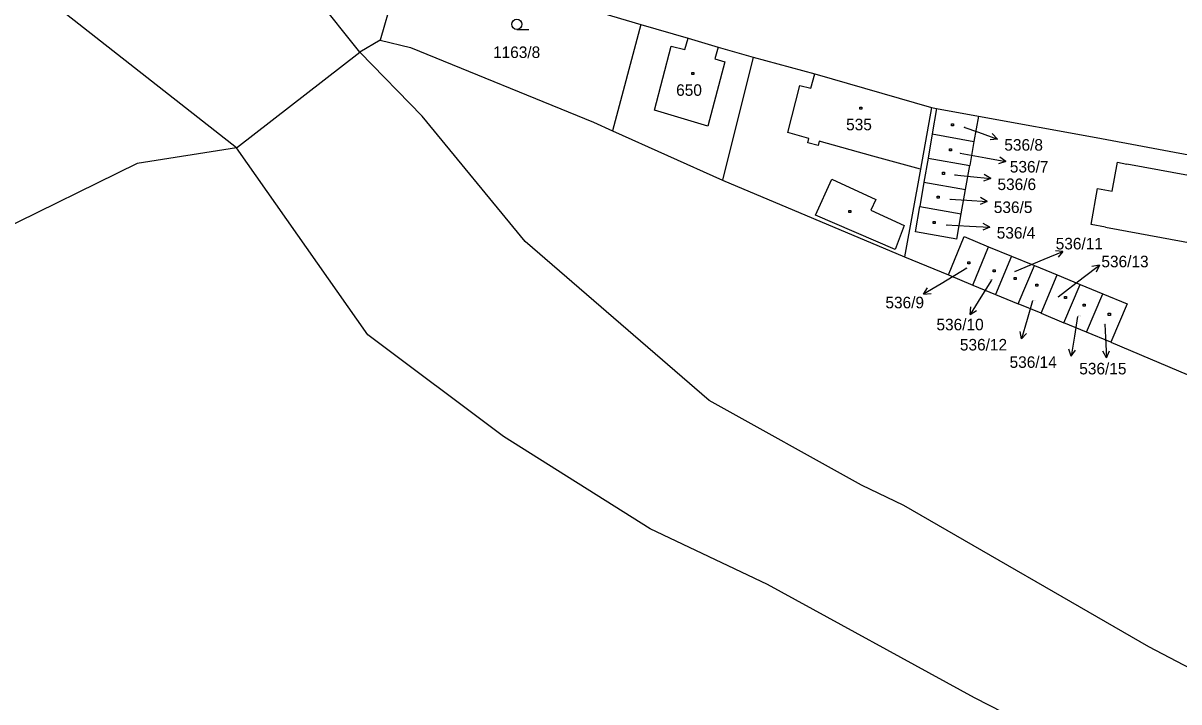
# Model space of a CAD drawing. Extents: x -795483 to -789093, y -1112258 to -1108741.
# Drawn here: x -792326 to -792155.7, y -1110149.8 to -1110049.9 of the extents above; entities that cross this region are included whole.
import ezdxf

# ---------------------------------------------------------------- set-up
doc = ezdxf.new("R2010")
doc.units = 0
for name, color, linetype in [('Komunikace', 7, 'Continuous'), ('Vrstva 1', 7, 'Continuous'), ('Vrstva 14', 7, 'Continuous'), ('Vrstva 15', 7, 'Continuous'), ('Vrstva 16', 7, 'Continuous'), ('Vrstva 2', 7, 'Continuous'), ('Vrstva 23', 7, 'Continuous'), ('Vrstva 25', 7, 'Continuous')]:
    doc.layers.add(name, color=color, linetype=linetype)

msp = doc.modelspace()

# ---------------------------------------------------------------- linework, layer by layer
at = {"layer": 'Komunikace'}
for p, q in [((-792187.44, -1110065.17), (-792185.28, -1110065.94)), ((-792187.97, -1110069.04), (-792184.17, -1110069.73)), ((-792188.78, -1110072.22), (-792186.45, -1110072.45)), ((-792189.49, -1110075.77), (-792186.99, -1110075.93)), ((-792190.04, -1110079.59), (-792186.57, -1110079.76)), ((-792179.91, -1110086.43), (-792175.58, -1110084.63)), ((-792186.99, -1110085.96), (-792190.78, -1110088.24)), ((-792173.51, -1110090.19), (-792169.83, -1110087.35)), ((-792183.36, -1110087.71), (-792184.9, -1110090.21)), ((-792177.3, -1110090.77), (-792178.09, -1110093.49)), ((-792170.66, -1110093.05), (-792171.13, -1110095.97)), ((-792166.66, -1110094.22), (-792166.56, -1110096.14))]:
    msp.add_line(p, q, dxfattribs=at)
at = {"layer": 'Vrstva 1'}
for p, q in [((-792294.56, -1110068.22), (-792338.95, -1110033.41)), ((-792276.39, -1110054.16), (-792289.1, -1110038.19)), ((-792269.72, -1110039.81), (-792273.43, -1110052.38)), ((-792269.72, -1110039.81), (-792234.98, -1110050.06)), ((-792234.98, -1110050.06), (-792239.19, -1110065.72)), ((-792234.98, -1110050.06), (-792228.04, -1110052.11)), ((-792273.43, -1110052.38), (-792276.39, -1110054.16)), ((-792273.43, -1110052.38), (-792268.94, -1110053.48)), ((-792228.04, -1110052.11), (-792223.61, -1110053.42)), ((-792294.56, -1110068.22), (-792276.39, -1110054.16)), ((-792267.24, -1110063.58), (-792276.39, -1110054.16)), ((-792268.94, -1110053.48), (-792241.96, -1110064.47)), ((-792223.61, -1110053.42), (-792218.43, -1110054.87)), ((-792218.43, -1110054.87), (-792222.98, -1110073.01)), ((-792218.43, -1110054.87), (-792209.35, -1110057.34)), ((-792209.35, -1110057.34), (-792192.18, -1110062.31)), ((-792252.06, -1110082.02), (-792267.24, -1110063.58)), ((-792192.18, -1110062.31), (-792193.82, -1110071.4)), ((-792192.18, -1110062.31), (-792191.44, -1110062.44)), ((-792191.44, -1110062.44), (-792192.08, -1110066.18)), ((-792191.44, -1110062.44), (-792185.28, -1110063.55)), ((-792185.28, -1110063.55), (-792185.93, -1110067.28)), ((-792185.28, -1110063.55), (-792167.93, -1110066.73)), ((-792241.96, -1110064.47), (-792239.19, -1110065.72)), ((-792239.19, -1110065.72), (-792222.98, -1110073.01)), ((-792192.08, -1110066.18), (-792192.69, -1110069.75)), ((-792192.08, -1110066.18), (-792185.93, -1110067.28)), ((-792167.93, -1110066.73), (-792119.01, -1110075.8)), ((-792294.56, -1110068.22), (-792309.21, -1110070.53)), ((-792275.24, -1110095.78), (-792294.56, -1110068.22)), ((-792185.93, -1110067.28), (-792186.55, -1110070.83)), ((-792192.69, -1110069.75), (-792193.3, -1110073.31)), ((-792192.69, -1110069.75), (-792186.55, -1110070.83)), ((-792165.57, -1110074.61), (-792164.79, -1110070.36)), ((-792164.79, -1110070.36), (-792163.39, -1110070.62)), ((-792309.21, -1110070.53), (-792356.78, -1110093.85)), ((-792193.82, -1110071.4), (-792196.16, -1110084.26)), ((-792187.17, -1110074.38), (-792186.55, -1110070.83)), ((-792145.08, -1110074), (-792163.39, -1110070.62)), ((-792222.98, -1110073.01), (-792196.16, -1110084.26)), ((-792193.3, -1110073.31), (-792193.91, -1110076.88)), ((-792193.3, -1110073.31), (-792187.17, -1110074.38)), ((-792187.79, -1110077.93), (-792187.17, -1110074.38)), ((-792168.64, -1110079.53), (-792167.73, -1110074.21)), ((-792167.73, -1110074.21), (-792165.57, -1110074.61)), ((-792194.55, -1110080.62), (-792193.91, -1110076.88)), ((-792193.91, -1110076.88), (-792187.79, -1110077.93)), ((-792188.44, -1110081.66), (-792187.79, -1110077.93)), ((-792166.54, -1110079.92), (-792168.64, -1110079.53)), ((-792166.54, -1110079.92), (-792146.82, -1110083.56)), ((-792224.96, -1110105.43), (-792252.06, -1110082.02)), ((-792188.44, -1110081.66), (-792194.55, -1110080.62)), ((-792186.09, -1110088.43), (-792183.76, -1110082.79)), ((-792183.76, -1110082.79), (-792180.39, -1110084.18)), ((-792196.16, -1110084.26), (-792189.7, -1110086.94)), ((-792180.39, -1110084.18), (-792182.74, -1110089.82)), ((-792180.39, -1110084.18), (-792177.03, -1110085.56)), ((-792179.39, -1110091.21), (-792177.03, -1110085.56)), ((-792177.03, -1110085.56), (-792173.66, -1110086.95)), ((-792189.7, -1110086.94), (-792186.09, -1110088.43)), ((-792176.04, -1110092.59), (-792173.66, -1110086.95)), ((-792173.66, -1110086.95), (-792170.29, -1110088.34)), ((-792186.09, -1110088.43), (-792182.74, -1110089.82)), ((-792172.69, -1110093.98), (-792170.29, -1110088.34)), ((-792170.29, -1110088.34), (-792166.92, -1110089.72)), ((-792182.74, -1110089.82), (-792179.39, -1110091.21)), ((-792169.33, -1110095.37), (-792166.92, -1110089.72)), ((-792166.92, -1110089.72), (-792163.33, -1110091.2)), ((-792176.04, -1110092.59), (-792179.39, -1110091.21)), ((-792163.33, -1110091.2), (-792165.77, -1110096.84)), ((-792176.04, -1110092.59), (-792172.69, -1110093.98)), ((-792169.33, -1110095.37), (-792172.69, -1110093.98)), ((-792255.24, -1110110.74), (-792275.24, -1110095.78)), ((-792165.77, -1110096.84), (-792169.33, -1110095.37)), ((-792165.77, -1110096.84), (-792152.88, -1110102.28)), ((-792202.48, -1110117.91), (-792224.96, -1110105.43)), ((-792233.64, -1110124.34), (-792255.24, -1110110.74)), ((-792196.27, -1110120.89), (-792202.48, -1110117.91)), ((-792160.15, -1110141.69), (-792196.27, -1110120.89)), ((-792216.32, -1110132.52), (-792233.64, -1110124.34)), ((-792185.85, -1110149.21), (-792216.32, -1110132.52)), ((-792117.26, -1110164.25), (-792160.15, -1110141.69)), ((-792168.85, -1110157.86), (-792185.85, -1110149.21))]:
    msp.add_line(p, q, dxfattribs=at)
msp.add_lwpolyline([(-792189.7, -1110086.94), (-792187.39, -1110081.3), (-792183.76, -1110082.79)], dxfattribs=at)
at = {"layer": 'Vrstva 16'}
for p, q in [((-792185.28, -1110065.94), (-792182.45, -1110066.95)), ((-792182.45, -1110066.95), (-792183.56, -1110067.08)), ((-792182.45, -1110066.95), (-792183.23, -1110066.14)), ((-792184.17, -1110069.73), (-792181.22, -1110070.27)), ((-792181.22, -1110070.27), (-792182.29, -1110070.58)), ((-792181.22, -1110070.27), (-792182.11, -1110069.6)), ((-792186.45, -1110072.45), (-792183.46, -1110072.75)), ((-792183.46, -1110072.75), (-792184.51, -1110073.15)), ((-792183.46, -1110072.75), (-792184.41, -1110072.15)), ((-792186.99, -1110075.93), (-792184, -1110076.13)), ((-792184, -1110076.13), (-792185.03, -1110076.56)), ((-792184, -1110076.13), (-792184.96, -1110075.56)), ((-792186.57, -1110079.76), (-792183.57, -1110079.9)), ((-792183.57, -1110079.9), (-792184.6, -1110080.35)), ((-792183.57, -1110079.9), (-792184.55, -1110079.36)), ((-792175.58, -1110084.63), (-792172.81, -1110083.48)), ((-792172.81, -1110083.48), (-792173.92, -1110083.4)), ((-792172.81, -1110083.48), (-792173.54, -1110084.32)), ((-792169.83, -1110087.35), (-792167.45, -1110085.52)), ((-792167.45, -1110085.52), (-792168.55, -1110085.73)), ((-792167.45, -1110085.52), (-792167.94, -1110086.52)), ((-792190.78, -1110088.24), (-792193.35, -1110089.78)), ((-792193.35, -1110089.78), (-792192.75, -1110088.84)), ((-792193.35, -1110089.78), (-792192.24, -1110089.7)), ((-792184.9, -1110090.21), (-792186.48, -1110092.76)), ((-792186.48, -1110092.76), (-792186.38, -1110091.65)), ((-792186.48, -1110092.76), (-792185.53, -1110092.17)), ((-792178.09, -1110093.49), (-792178.92, -1110096.37)), ((-792178.92, -1110096.37), (-792179.13, -1110095.27)), ((-792178.92, -1110096.37), (-792178.17, -1110095.55)), ((-792171.13, -1110095.97), (-792171.61, -1110098.93)), ((-792166.56, -1110096.14), (-792166.41, -1110099.14)), ((-792171.61, -1110098.93), (-792171.94, -1110097.86)), ((-792171.61, -1110098.93), (-792170.96, -1110098.02)), ((-792166.41, -1110099.14), (-792166.96, -1110098.16)), ((-792166.41, -1110099.14), (-792165.96, -1110098.11))]:
    msp.add_line(p, q, dxfattribs=at)
at = {"layer": 'Vrstva 2'}
for p, q in [((-792233.01, -1110062.7), (-792230.52, -1110053.26)), ((-792230.52, -1110053.26), (-792228.52, -1110053.78)), ((-792228.52, -1110053.78), (-792228.04, -1110052.11)), ((-792223.61, -1110053.42), (-792224.11, -1110055.15)), ((-792222.61, -1110055.55), (-792225.15, -1110065.04)), ((-792224.11, -1110055.15), (-792222.61, -1110055.55)), ((-792209.96, -1110059.45), (-792209.35, -1110057.34)), ((-792213.34, -1110065.99), (-792211.58, -1110059.04)), ((-792211.58, -1110059.04), (-792209.96, -1110059.45)), ((-792225.15, -1110065.04), (-792233.01, -1110062.7)), ((-792210.26, -1110066.84), (-792213.34, -1110065.99)), ((-792210.4, -1110067.48), (-792210.26, -1110066.84)), ((-792208.89, -1110067.91), (-792210.4, -1110067.48)), ((-792208.71, -1110067.27), (-792208.89, -1110067.91)), ((-792200.8, -1110069.46), (-792208.71, -1110067.27)), ((-792193.82, -1110071.4), (-792200.8, -1110069.46)), ((-792209.26, -1110078.14), (-792206.88, -1110072.87)), ((-792206.88, -1110072.87), (-792200.38, -1110075.85)), ((-792200.38, -1110075.85), (-792201.1, -1110077.42)), ((-792197.52, -1110083.2), (-792209.26, -1110078.14)), ((-792201.1, -1110077.42), (-792196.21, -1110079.67)), ((-792196.21, -1110079.67), (-792197.52, -1110083.2))]:
    msp.add_line(p, q, dxfattribs=at)
at = {"layer": 'Vrstva 23'}
msp.add_line((-792253.27, -1110050.8), (-792251.52, -1110050.8), dxfattribs=at)
msp.add_circle((-792253.27, -1110050.05), 0.75, dxfattribs=at)
at = {"layer": 'Vrstva 25'}
for p, q in [((-792227.49, -1110057.12), (-792227.19, -1110057.12)), ((-792227.49, -1110057.42), (-792227.49, -1110057.12)), ((-792227.19, -1110057.42), (-792227.49, -1110057.42)), ((-792227.19, -1110057.12), (-792227.19, -1110057.42)), ((-792202.75, -1110062.23), (-792202.45, -1110062.23)), ((-792202.75, -1110062.53), (-792202.75, -1110062.23)), ((-792202.45, -1110062.53), (-792202.75, -1110062.53)), ((-792202.45, -1110062.23), (-792202.45, -1110062.53)), ((-792189.22, -1110064.69), (-792188.92, -1110064.69)), ((-792189.22, -1110064.99), (-792189.22, -1110064.69)), ((-792188.92, -1110064.99), (-792189.22, -1110064.99)), ((-792188.92, -1110064.69), (-792188.92, -1110064.99)), ((-792189.53, -1110068.39), (-792189.23, -1110068.39)), ((-792189.53, -1110068.69), (-792189.53, -1110068.39)), ((-792189.23, -1110068.69), (-792189.53, -1110068.69)), ((-792189.23, -1110068.39), (-792189.23, -1110068.69)), ((-792190.56, -1110071.84), (-792190.26, -1110071.84)), ((-792190.56, -1110072.14), (-792190.56, -1110071.84)), ((-792190.26, -1110071.84), (-792190.26, -1110072.14)), ((-792190.26, -1110072.14), (-792190.56, -1110072.14)), ((-792191.33, -1110075.34), (-792191.03, -1110075.34)), ((-792191.33, -1110075.64), (-792191.33, -1110075.34)), ((-792191.03, -1110075.34), (-792191.03, -1110075.64)), ((-792191.03, -1110075.64), (-792191.33, -1110075.64)), ((-792204.36, -1110077.45), (-792204.06, -1110077.45)), ((-792204.36, -1110077.75), (-792204.36, -1110077.45)), ((-792204.06, -1110077.75), (-792204.36, -1110077.75)), ((-792204.06, -1110077.45), (-792204.06, -1110077.75)), ((-792191.95, -1110079.08), (-792191.65, -1110079.08)), ((-792191.95, -1110079.38), (-792191.95, -1110079.08)), ((-792191.65, -1110079.38), (-792191.95, -1110079.38)), ((-792191.65, -1110079.08), (-792191.65, -1110079.38)), ((-792186.81, -1110085.03), (-792186.51, -1110085.03)), ((-792186.81, -1110085.33), (-792186.81, -1110085.03)), ((-792186.51, -1110085.33), (-792186.81, -1110085.33)), ((-792186.51, -1110085.03), (-792186.51, -1110085.33)), ((-792183.1, -1110086.19), (-792182.8, -1110086.19)), ((-792183.1, -1110086.49), (-792183.1, -1110086.19)), ((-792182.8, -1110086.49), (-792183.1, -1110086.49)), ((-792182.8, -1110086.19), (-792182.8, -1110086.49)), ((-792180.01, -1110087.34), (-792179.71, -1110087.34)), ((-792180.01, -1110087.64), (-792180.01, -1110087.34)), ((-792179.71, -1110087.34), (-792179.71, -1110087.64)), ((-792179.71, -1110087.64), (-792180.01, -1110087.64)), ((-792176.8, -1110088.29), (-792176.5, -1110088.29)), ((-792176.8, -1110088.59), (-792176.8, -1110088.29)), ((-792176.5, -1110088.59), (-792176.8, -1110088.59)), ((-792176.5, -1110088.29), (-792176.5, -1110088.59)), ((-792172.59, -1110090.11), (-792172.29, -1110090.11)), ((-792172.59, -1110090.41), (-792172.59, -1110090.11)), ((-792172.29, -1110090.41), (-792172.59, -1110090.41)), ((-792172.29, -1110090.11), (-792172.29, -1110090.41)), ((-792169.82, -1110091.24), (-792169.52, -1110091.24)), ((-792169.82, -1110091.54), (-792169.82, -1110091.24)), ((-792169.52, -1110091.54), (-792169.82, -1110091.54)), ((-792169.52, -1110091.24), (-792169.52, -1110091.54)), ((-792166.13, -1110092.6), (-792165.83, -1110092.6)), ((-792166.13, -1110092.9), (-792166.13, -1110092.6)), ((-792165.83, -1110092.9), (-792166.13, -1110092.9)), ((-792165.83, -1110092.6), (-792165.83, -1110092.9))]:
    msp.add_line(p, q, dxfattribs=at)

# ---------------------------------------------------------------- texts
at = {"layer": 'Vrstva 14'}
msp.add_text('1163/8', height=1.7, dxfattribs=at).set_placement((-792256.78, -1110055.01))
at = {"layer": 'Vrstva 15'}
for s, height, p in [('650', 1.7, (-792229.8, -1110060.58)), ('535', 1.7, (-792204.76, -1110065.65)), ('536/8', 0.1, (-792187.44, -1110065.17)), ('536/7', 0.1, (-792188.18, -1110069.04)), ('536/6', 0.1, (-792188.78, -1110072.22)), ('536/5', 0.1, (-792189.49, -1110075.77)), ('536/4', 0.1, (-792190.04, -1110079.59)), ('536/9', 0.1, (-792187.2, -1110085.96)), ('536/11', 0.1, (-792180.13, -1110086.43)), ('536/10', 0.1, (-792183.6, -1110087.71)), ('536/12', 0.1, (-792177.3, -1110090.77)), ('536/13', 0.1, (-792173.75, -1110090.19)), ('536/14', 0.1, (-792170.66, -1110093.05)), ('536/15', 0.1, (-792166.9, -1110094.22))]:
    msp.add_text(s, height=height, dxfattribs=at).set_placement(p)
at = {"layer": 'Vrstva 16'}
for s, p in [('536/8', (-792181.45, -1110068.65)), ('536/7', (-792180.64, -1110071.87)), ('536/6', (-792182.46, -1110074.45)), ('536/5', (-792183, -1110077.83)), ('536/4', (-792182.57, -1110081.6)), ('536/11', (-792173.88, -1110083.19)), ('536/13', (-792167.15, -1110085.82)), ('536/9', (-792198.97, -1110091.86)), ('536/10', (-792191.45, -1110095.1)), ('536/12', (-792188, -1110098.07)), ('536/14', (-792180.68, -1110100.63)), ('536/15', (-792170.41, -1110101.59))]:
    msp.add_text(s, height=1.7, dxfattribs=at).set_placement(p)

doc.saveas('drawing.dxf')
